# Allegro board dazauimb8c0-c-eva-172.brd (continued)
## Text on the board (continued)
User.45: FIGURE | TYPE | Oblong | Rectangle | Circle | SIZE | 43.0x20.0 | 59.0x20.0 | 59.0x28.0 | 63.0x31.0 | 71.0x31.0 | 75.0x39.0 | 91.0x28.0 | 102.0x31.0 | 118.0x20.0 | 252.0x232.0 | 157.0x157.0 | 10.0 | 12.0 | 14.0 | 18.0 | 22.0 | 32.0 | 35.0 | 102.0 | 118.0 | 126.0 | 150.0 | 220.0 | 41.0 | 43.0 | 47.0 | 63.0 | 67.0 | 75.0 | 98.0 | DRILL CHART: TOP to BOTTOM | ALL UNITS ARE IN MILS | PLATED | NON-PLATED | ROTATION | 90.000 | 0.000 | - | QTY | 2 | 6 | 4 | 1 | 33 | 5708 | 19 | 5 | 322 | 48 | 10 | 18 | 8 | 3 | 6178 | TOTAL HOLES:
